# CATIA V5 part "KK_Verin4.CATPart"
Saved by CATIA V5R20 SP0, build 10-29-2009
Part number: Verin4
Bounding box of the stored display mesh (mm): x 40.925 to 55.294, y -91.425 to -56.931, z -5 to 66.399
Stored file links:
  G:\Khaled_CFAO_2011\ST2M\ST2M_GR1\msallin\Khaled\Version_Finale\KK_Verin4.CATPart
  C:\Users\Mathieu\Desktop\Think Motion\JOUG-MELEE2.CATProduct
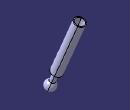
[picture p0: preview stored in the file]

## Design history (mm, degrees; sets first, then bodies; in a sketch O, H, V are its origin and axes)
External parameters (linked from other documents)
  `External.Taille du joug` = 100 mm
Set1
  Line1: linked copy from another document
  Line2: linked copy from another document
  Point1: linked copy from another document
Set2
  Plane1: type 2Lines, Element1 Line1, Element2 Line2
  Plane2: type 2Lines, Element1 Sketch1.L2, Element2 Sketch1.L4
  Point2: type Center, Curve Sketch1
  DatumSurface1
Body1 (main body)
  Sketch1 on Plane1, origin (70.7263, -40.514, 20.3771), H (-0.4971, -0.8677, 0), V (-0.2105, 0.1206, 0.9701)
    point P1 (48.3959, -6.5464)
    line L1 (48.3959, -6.5464) -> (50.7963, -5.8477)
    line L2 (50.7963, -5.8477) -> (35.4266, 46.9611)
    line L3 (35.4266, 46.9611) -> (34.6265, 46.7282)
    line L4 (34.6265, 46.7282) -> (46.9222, 4.4812)
    line L5 (46.9222, 4.4812) -> (42.9216, 3.3168)
    point P6 (42.9216, 3.3168)
    line L6 (48.3959, -6.5464) -> (51.1904, -16.148)
    point P7 (48.3959, -6.5464)
    arc A1 centre (50, -21.0042) radius 5 from (51.3972, -25.805) to (51.1904, -16.148) ccw
    point P9 (50, -21.0042)
    point P10 (51.3972, -25.805)
    reference projected line E1 (20, 82.0734) -> (50, -21.0042) from Line1
    reference projected line E2 (20, 82.0734) -> (50, -21.0042) from Line1
    reference projected line E3 (20, 82.0734) -> (50, -21.0042) from Line1
    reference projected point E4 (50, -21.0042) from Point1
    reference projected line E5 (20, 82.0734) -> (50, -21.0042) from Line1
    length L2 = 55 {= `External.Taille du joug` *(7/10-1/10-1/20)}
    length L4 = 44 {= Sketch1.length(L2) *4/5}
    distance L2 E1 = 5 {= `External.Taille du joug` /20}
    distance L4 E2 = 4.1667 {= `External.Taille du joug` /24}
    distance P6 E3 = 0
    length L1 = 2.5 {= `External.Taille du joug` /40}
    length L6 = 10 {= `External.Taille du joug` /10}
    distance P9 E4 = 0
    radius A1 = 5 {= `External.Taille du joug` /20}
    distance P10 E5 = 0
    perpendicularity: L2 L1
    parallelism: L3 L1, L4 L2, L5 L1, L6 L4
    coincidence: P1 P7
  Shaft1: profile Sketch1, axis Line1, angle 360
